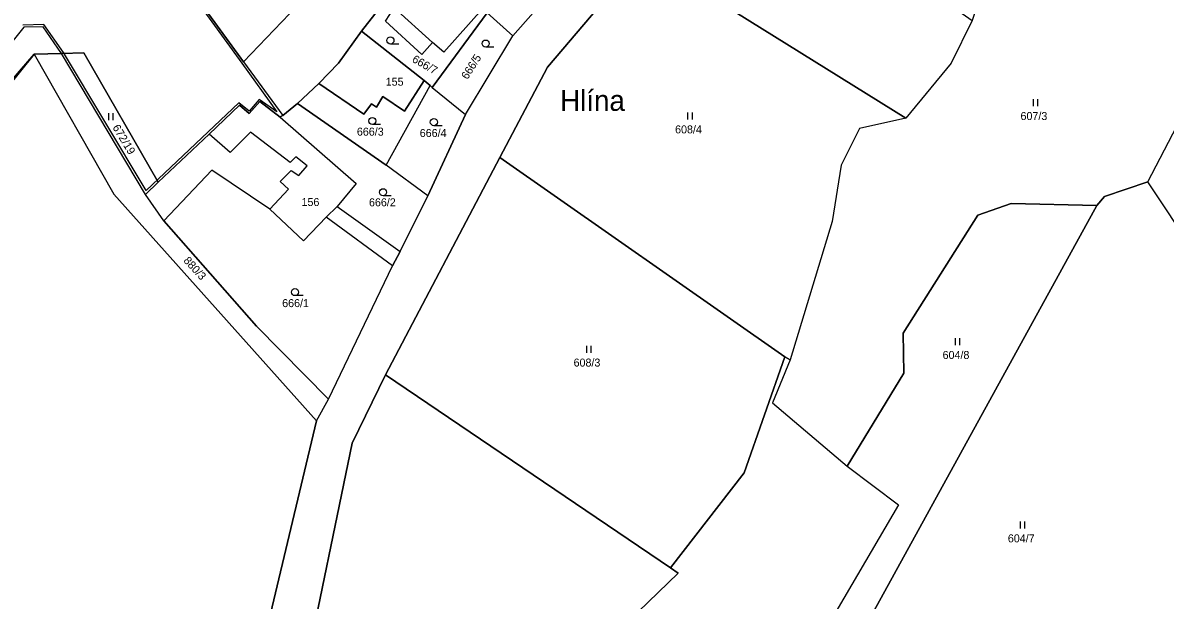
# Model space of a CAD drawing. Extents: x -654083 to -650132, y -1099819 to -1096699.
# Drawn here: x -651993.4 to -651750.7, y -1099244.9 to -1099122.2 of the extents above; entities that cross this region are included whole.
import ezdxf

# ---------------------------------------------------------------- set-up
doc = ezdxf.new("R2010")
doc.units = 0
for name, color, linetype in [('Hranice - vnitř_ kresba', 7, 'Continuous'), ('Názvy', 7, 'Continuous'), ('Obvody jako plochy', 7, 'Continuous'), ('Ostatní hranice', 7, 'Continuous'), ('Parcelní čísla', 7, 'Continuous'), ('Značky kultur', 7, 'Continuous')]:
    doc.layers.add(name, color=color, linetype=linetype)

msp = doc.modelspace()

# ---------------------------------------------------------------- linework, layer by layer
at = {"layer": 'Hranice - vnitř_ kresba'}
for p, q in [((-651906.34, -1099126.41), (-651914.49, -1099119.01)), ((-651949.33, -1099149.79), (-651953.83, -1099145.88)), ((-651945, -1099145.46), (-651949.33, -1099149.79)), ((-651936.56, -1099151.88), (-651945, -1099145.46)), ((-651935.36, -1099150.68), (-651936.56, -1099151.88)), ((-651932.96, -1099152.61), (-651935.36, -1099150.68)), ((-651938.69, -1099155.95), (-651936.35, -1099153.6)), ((-651936.35, -1099153.6), (-651934.73, -1099154.64)), ((-651934.73, -1099154.64), (-651932.96, -1099152.61)), ((-651936.97, -1099157.56), (-651938.69, -1099155.95)), ((-651940.93, -1099161.82), (-651936.97, -1099157.56)), ((-651926.58, -1099161.22), (-651928.93, -1099163.55))]:
    msp.add_line(p, q, dxfattribs=at)
at = {"layer": 'Obvody jako plochy'}
for points in [[(-651746.85, -1098984.89), (-651766.34, -1099002.76), (-651779.23, -1099016.37), (-651792.49, -1099032.81), (-651807.93, -1099044.72), (-651818.46, -1099057.74), (-651819.53, -1099059.16), (-651833.37, -1099076.43), (-651842.69, -1099085.85), (-651861.59, -1099107.7), (-651881.94, -1099131.6), (-651892.09, -1099150.81), (-651916.35, -1099197.07), (-651923.42, -1099211.56), (-651933.81, -1099262.02)], [(-651997.42, -1099105.77), (-651982.14, -1099108.69), (-651973.27, -1099110.1), (-651968.03, -1099100.87), (-651946.49, -1099130.48), (-651938.16, -1099141.93), (-651938.71, -1099142.29), (-651943.03, -1099138.95), (-651945.28, -1099141.45), (-651947.36, -1099139.73), (-651953.83, -1099145.88), (-651964.62, -1099156.06), (-651980.39, -1099128.55), (-651985.16, -1099128.75), (-651989.08, -1099123.03), (-651993.14, -1099123.13), (-652100.46, -1099256.77)], [(-651942.97, -1099257.07), (-651930.97, -1099206.79), (-651928.43, -1099202.19), (-651914.85, -1099173.88), (-651913.23, -1099170.8), (-651907.38, -1099158.95), (-651899.38, -1099141.68), (-651889.31, -1099124.96), (-651875.74, -1099109.58)], [(-651866.95, -1099251.5), (-651854.18, -1099239.22), (-651855.8, -1099238.1), (-651840.19, -1099217.87), (-651831.53, -1099193.2), (-651830.39, -1099193.87), (-651834.11, -1099202.99), (-651818.3, -1099216.42), (-651807.4, -1099224.67), (-651837.64, -1099276.35)]]:
    msp.add_lwpolyline(points, dxfattribs=at)
for points in [[(-651913.47, -1099113.68), (-651915.2, -1099112.22), (-651911.37, -1099106.96), (-651909.45, -1099108.15), (-651897.34, -1099093.49), (-651903.83, -1099085.44), (-651915.71, -1099098.28), (-651928.62, -1099111.78), (-651936.76, -1099120.3), (-651946.49, -1099130.48), (-651938.16, -1099141.93), (-651935.02, -1099139.34), (-651930.53, -1099135.13), (-651926.34, -1099130.8), (-651921.46, -1099123.99)], [(-651842.69, -1099085.85), (-651791.74, -1099121.71), (-651796.17, -1099130.75), (-651805.83, -1099142.49), (-651861.59, -1099107.7)], [(-651961.43, -1099087.83), (-651936.76, -1099120.3), (-651946.49, -1099130.48), (-651968.03, -1099100.87)], [(-651764.69, -1099106.64), (-651782.92, -1099095.75), (-651791.74, -1099121.71), (-651796.17, -1099130.75), (-651805.83, -1099142.49), (-651815.66, -1099144.65), (-651819.54, -1099152.46), (-651821.46, -1099164.45), (-651830.39, -1099193.87), (-651834.11, -1099202.99), (-651818.3, -1099216.42), (-651806.26, -1099196.66), (-651806.37, -1099188.16), (-651790.55, -1099163.1), (-651783.46, -1099160.62), (-651765.25, -1099161.01), (-651763.63, -1099159.11), (-651754.44, -1099156.03), (-651742.95, -1099133.97), (-651740.8, -1099123.07)], [(-651889.31, -1099124.96), (-651875.74, -1099109.58), (-651881.55, -1099105.02), (-651886.4, -1099111.33), (-651889.22, -1099109.35), (-651890.57, -1099110.86), (-651893.8, -1099108.83), (-651895.47, -1099110.44), (-651902.93, -1099107.16), (-651906.78, -1099110.44), (-651895.84, -1099119.27), (-651894.75, -1099120.11)], [(-651909.45, -1099108.15), (-651906.78, -1099110.44), (-651895.84, -1099119.27), (-651903.94, -1099128.43), (-651906.34, -1099126.41), (-651908.64, -1099128.92), (-651916.35, -1099121.82), (-651914.49, -1099119.01), (-651911.54, -1099115.46), (-651913.47, -1099113.68)], [(-651906.34, -1099126.41), (-651914.49, -1099119.01), (-651911.54, -1099115.46), (-651913.47, -1099113.68), (-651915.2, -1099112.22), (-651911.37, -1099106.96), (-651909.45, -1099108.15), (-651906.78, -1099110.44), (-651895.84, -1099119.27), (-651903.94, -1099128.43)], [(-651819.54, -1099152.46), (-651821.46, -1099164.45), (-651830.39, -1099193.87), (-651831.53, -1099193.2), (-651892.09, -1099150.81), (-651881.94, -1099131.6), (-651861.59, -1099107.7), (-651805.83, -1099142.49), (-651815.66, -1099144.65)], [(-651914.49, -1099119.01), (-651911.54, -1099115.46), (-651913.47, -1099113.68), (-651921.46, -1099123.99), (-651908.15, -1099134.45), (-651906.87, -1099135.55), (-651906.43, -1099135.96), (-651894.75, -1099120.11), (-651895.84, -1099119.27), (-651903.94, -1099128.43), (-651906.34, -1099126.41), (-651908.64, -1099128.92), (-651916.35, -1099121.82)], [(-651899.38, -1099141.68), (-651889.31, -1099124.96), (-651894.75, -1099120.11), (-651906.43, -1099135.96)], [(-652247.17, -1099388.87), (-652240.49, -1099388.17), (-652194.6, -1099348.51), (-652105.79, -1099269.3), (-652101.71, -1099265.69), (-652096.27, -1099259.88), (-652096.92, -1099258.75), (-652011.11, -1099152.13), (-651990.98, -1099128.85), (-651985.16, -1099128.75), (-651989.08, -1099123.03), (-651993.14, -1099123.13), (-652100.46, -1099256.77), (-652199.43, -1099348.5)], [(-651908.15, -1099134.45), (-651921.46, -1099123.99), (-651926.34, -1099130.8), (-651930.53, -1099135.13), (-651920.97, -1099141.63), (-651919.35, -1099139.42), (-651918.27, -1099140.12), (-651916.91, -1099137.9), (-651912.29, -1099141)], [(-651912.29, -1099141), (-651916.91, -1099137.9), (-651918.27, -1099140.12), (-651919.35, -1099139.42), (-651920.97, -1099141.63), (-651930.53, -1099135.13), (-651926.34, -1099130.8), (-651921.46, -1099123.99), (-651908.15, -1099134.45)], [(-652096.27, -1099259.88), (-652096.92, -1099258.75), (-652011.11, -1099152.13), (-651990.98, -1099128.85)], [(-651965.81, -1099327.75), (-651983.1, -1099356.47), (-651993.06, -1099349.81), (-652009.25, -1099338.64), (-652019.5, -1099327.72), (-652034.55, -1099313.15), (-652044.03, -1099305.74), (-652069.2, -1099285.12), (-652096.27, -1099259.88), (-651990.98, -1099128.85), (-651974.06, -1099158.6), (-651930.97, -1099206.79), (-651942.97, -1099257.07), (-651959.92, -1099306.18)], [(-651930.97, -1099206.79), (-651928.43, -1099202.19), (-651943.71, -1099186.68), (-651963.45, -1099164.3), (-651967.34, -1099158.72), (-651985.16, -1099128.75), (-651990.98, -1099128.85), (-651974.06, -1099158.6)], [(-651964.62, -1099156.06), (-651967.34, -1099158.72), (-651985.16, -1099128.75), (-651980.39, -1099128.55)], [(-651906.87, -1099135.55), (-651908.15, -1099134.45), (-651912.29, -1099141), (-651916.91, -1099137.9), (-651918.27, -1099140.12), (-651919.35, -1099139.42), (-651920.97, -1099141.63), (-651930.53, -1099135.13), (-651935.02, -1099139.34), (-651916.19, -1099152.5)], [(-651742.95, -1099133.97), (-651696.01, -1099178.77), (-651705.09, -1099202.68), (-651715.16, -1099198.65), (-651734.73, -1099185.66), (-651754.44, -1099156.03)], [(-651906.43, -1099135.96), (-651899.38, -1099141.68), (-651907.38, -1099158.95), (-651916.19, -1099152.5), (-651906.87, -1099135.55)], [(-651926.58, -1099161.22), (-651913.23, -1099170.8), (-651914.85, -1099173.88), (-651928.93, -1099163.55), (-651933.74, -1099168.58), (-651940.93, -1099161.82), (-651953.2, -1099153.53), (-651963.45, -1099164.3), (-651967.34, -1099158.72), (-651964.62, -1099156.06), (-651953.83, -1099145.88), (-651947.36, -1099139.73), (-651945.28, -1099141.45), (-651943.03, -1099138.95), (-651938.71, -1099142.29), (-651922.54, -1099156.37)], [(-651953.83, -1099145.88), (-651947.36, -1099139.73), (-651945.28, -1099141.45), (-651943.03, -1099138.95), (-651938.71, -1099142.29), (-651922.54, -1099156.37), (-651926.58, -1099161.22), (-651928.93, -1099163.55), (-651933.74, -1099168.58), (-651940.93, -1099161.82), (-651936.97, -1099157.56), (-651938.69, -1099155.95), (-651936.35, -1099153.6), (-651934.73, -1099154.64), (-651932.96, -1099152.61), (-651935.36, -1099150.68), (-651936.56, -1099151.88), (-651945, -1099145.46), (-651949.33, -1099149.79)], [(-651913.23, -1099170.8), (-651907.38, -1099158.95), (-651916.19, -1099152.5), (-651935.02, -1099139.34), (-651938.16, -1099141.93), (-651938.71, -1099142.29), (-651922.54, -1099156.37), (-651926.58, -1099161.22)], [(-651892.09, -1099150.81), (-651831.53, -1099193.2), (-651840.19, -1099217.87), (-651855.8, -1099238.1), (-651916.35, -1099197.07)], [(-651928.93, -1099163.55), (-651933.74, -1099168.58), (-651940.93, -1099161.82), (-651953.2, -1099153.53), (-651963.45, -1099164.3), (-651943.71, -1099186.68), (-651928.43, -1099202.19), (-651914.85, -1099173.88)], [(-651788.88, -1099294.36), (-651775.45, -1099293.6), (-651747.01, -1099245.51), (-651715.16, -1099198.65), (-651734.73, -1099185.66), (-651754.44, -1099156.03), (-651763.63, -1099159.11), (-651765.25, -1099161.01), (-651829.81, -1099278.57)], [(-651783.46, -1099160.62), (-651790.55, -1099163.1), (-651806.37, -1099188.16), (-651806.26, -1099196.66), (-651818.3, -1099216.42), (-651807.4, -1099224.67), (-651837.64, -1099276.35), (-651829.81, -1099278.57), (-651765.25, -1099161.01)], [(-651956.84, -1099333.41), (-651949.78, -1099308.04), (-651933.81, -1099262.02), (-651923.42, -1099211.56), (-651916.35, -1099197.07), (-651855.8, -1099238.1), (-651854.18, -1099239.22), (-651866.95, -1099251.5), (-651877.79, -1099256.11), (-651888.13, -1099262.59), (-651894.74, -1099274.8), (-651903.83, -1099284.52), (-651924.14, -1099307.57), (-651935.26, -1099324.62), (-651942.33, -1099332.61), (-651948.22, -1099335.93)]]:
    msp.add_lwpolyline(points, close=True, dxfattribs=at)
at = {"layer": 'Ostatní hranice'}
for p, q in [((-651970.11, -1099098.51), (-651946.88, -1099130.79)), ((-651988.93, -1099122.55), (-651993.4, -1099122.7)), ((-651984.74, -1099128.48), (-651988.93, -1099122.55)), ((-651967.21, -1099157.82), (-651984.74, -1099128.48)), ((-651946.88, -1099130.79), (-651939.41, -1099141.1)), ((-651947.47, -1099139.22), (-651967.21, -1099157.82)), ((-651945.29, -1099140.95), (-651947.47, -1099139.22)), ((-651943.19, -1099138.48), (-651945.29, -1099140.95)), ((-651939.41, -1099141.1), (-651943.19, -1099138.48))]:
    msp.add_line(p, q, dxfattribs=at)
at = {"layer": 'Značky kultur'}
for p, q in [((-651913.54, -1099126.71), (-651915.29, -1099126.71)), ((-651893.31, -1099127.36), (-651895.06, -1099127.36)), ((-651778.78, -1099138.44), (-651778.78, -1099139.94)), ((-651777.76, -1099139.94), (-651777.76, -1099138.44)), ((-651975.19, -1099141.42), (-651975.19, -1099142.92)), ((-651974.17, -1099142.92), (-651974.17, -1099141.42)), ((-651852.17, -1099141.27), (-651852.17, -1099142.77)), ((-651851.15, -1099142.77), (-651851.15, -1099141.27)), ((-651917.38, -1099143.82), (-651919.13, -1099143.82)), ((-651904.32, -1099144.07), (-651906.07, -1099144.07)), ((-651915.11, -1099158.97), (-651916.86, -1099158.97)), ((-651933.82, -1099180.2), (-651935.57, -1099180.2)), ((-651873.66, -1099190.84), (-651873.66, -1099192.34)), ((-651872.64, -1099192.34), (-651872.64, -1099190.84)), ((-651795.35, -1099189.23), (-651795.35, -1099190.73)), ((-651794.33, -1099190.73), (-651794.33, -1099189.23)), ((-651781.55, -1099228.22), (-651781.55, -1099229.72)), ((-651780.53, -1099229.72), (-651780.53, -1099228.22))]:
    msp.add_line(p, q, dxfattribs=at)
for centre in [(-651915.29, -1099125.96), (-651895.06, -1099126.61), (-651919.13, -1099143.07), (-651906.07, -1099143.32), (-651916.86, -1099158.22), (-651935.57, -1099179.45)]:
    msp.add_circle(centre, 0.75, dxfattribs=at)

# ---------------------------------------------------------------- texts
at = {"layer": 'Názvy'}
msp.add_text('Hlína', height=4.4, dxfattribs=at).set_placement((-651879.24, -1099140.92))
at = {"layer": 'Parcelní čísla'}
for s, rotation, p in [('666/7', 330.111, (-651910.85, -1099130.41)), ('666/5', 57.627, (-651898.94, -1099134.38)), ('672/19', 301.05, (-651974.4, -1099144.44)), ('880/3', 312.354, (-651959.36, -1099172.85))]:
    msp.add_text(s, height=1.7, rotation=rotation, dxfattribs=at).set_placement(p)
for s, p in [('155', (-651916.3, -1099135.57)), ('607/3', (-651781.46, -1099142.87)), ('666/3', (-651922.42, -1099146.19)), ('666/4', (-651909.07, -1099146.48)), ('608/4', (-651854.83, -1099145.71)), ('156', (-651934.18, -1099161.15)), ('666/2', (-651919.85, -1099161.21)), ('666/1', (-651938.29, -1099182.64)), ('608/3', (-651876.39, -1099195.28)), ('604/8', (-651798.01, -1099193.66)), ('604/7', (-651784.15, -1099232.65))]:
    msp.add_text(s, height=1.7, dxfattribs=at).set_placement(p)

doc.saveas('drawing.dxf')
